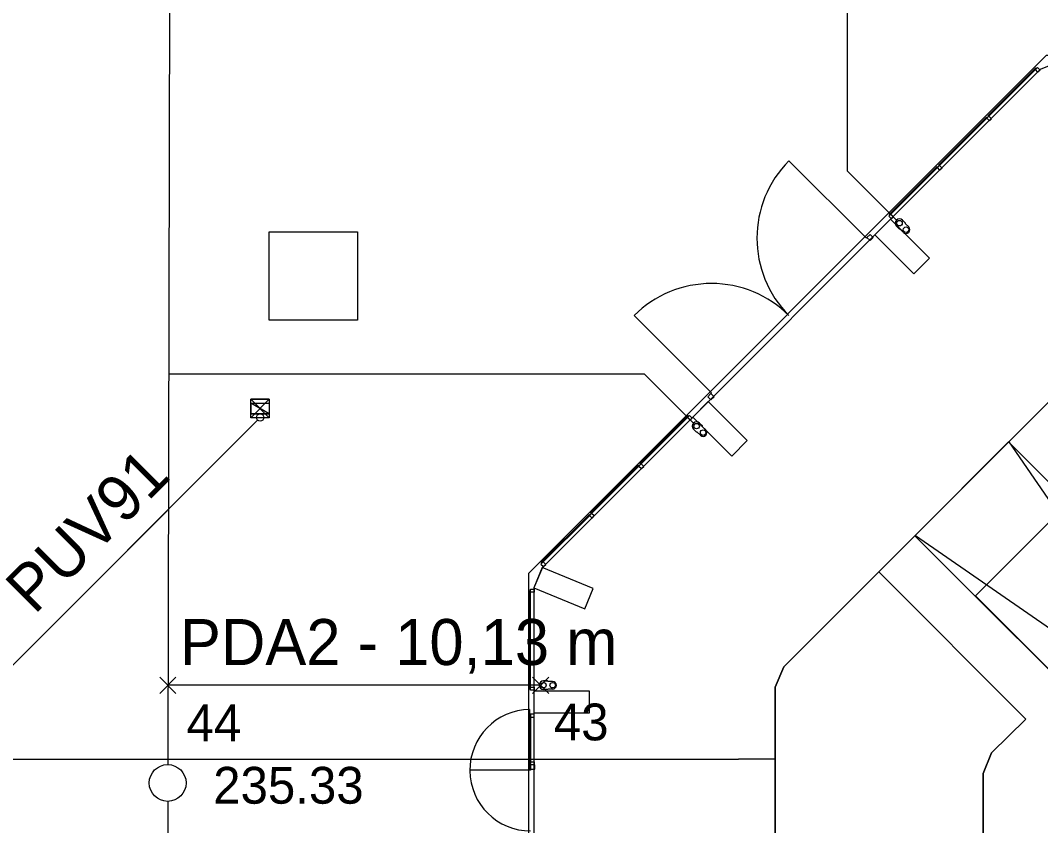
# Model space of a CAD drawing. Extents: x -264234 to -263604, y -1242346 to -1242049.
# Drawn here: x -263922.86 to -263895.13, y -1242108.24 to -1242086.36 of the extents above; entities that cross this region are included whole.
import ezdxf

# ---------------------------------------------------------------- set-up
doc = ezdxf.new("R2010")
doc.units = 0
for name, color, linetype in [('KFA_BODY_CISLO', 7, 'Continuous'), ('KFA_BODY_SYMBOL', 7, 'Continuous'), ('KFA_BODY_VYSKA', 7, 'Continuous'), ('KFA_DAZDOVA_KANALIZACIA_pripojky_tA_tC', 7, 'Continuous'), ('KFA_DAZDOVA_KANALIZACIA_pripojky_tA_tC_popis', 7, 'Continuous'), ('KFA_JESTV_IS_DSP_-_KANAL_DAZD', 7, 'Continuous'), ('KFA_SITUACIA_DSP', 7, 'Continuous'), ('KFA_SO_40-2-II_DK_PRIPOJKY_UV_PROJEKT', 7, 'Continuous'), ('KFA_SO_40-2-II_DK_PRIPOJKY_UV_PROJEKT_popis', 7, 'Continuous'), ('KFA_SO_40-2-II_DK_UV_PROJEKT', 7, 'Continuous')]:
    doc.layers.add(name, color=color, linetype=linetype)

msp = doc.modelspace()

# ---------------------------------------------------------------- linework, layer by layer
at = {"layer": 'KFA_BODY_SYMBOL'}
for p, q in [((-263919.072, -1242104.649), (-263918.63, -1242104.207)), ((-263918.63, -1242104.649), (-263919.072, -1242104.207)), ((-263908.939, -1242104.648), (-263908.497, -1242104.206)), ((-263908.497, -1242104.648), (-263908.939, -1242104.206))]:
    msp.add_line(p, q, dxfattribs=at)
at = {"layer": 'KFA_DAZDOVA_KANALIZACIA_pripojky_tA_tC'}
msp.add_line((-263908.718, -1242104.427), (-263918.851, -1242104.428), dxfattribs=at)
at = {"layer": 'KFA_JESTV_IS_DSP_-_KANAL_DAZD'}
for p, q in [((-263918.803, -1242082.338), (-263918.855, -1242106.583)), ((-263918.855, -1242107.583), (-263918.765, -1242151.564))]:
    msp.add_line(p, q, dxfattribs=at)
msp.add_circle((-263918.856, -1242107.083), 0.5, dxfattribs=at)
at = {"layer": 'KFA_SITUACIA_DSP'}
for p, q in [((-263900.379, -1242090.456), (-263900.379, -1242081.705)), ((-263908.663, -1242101.215), (-263895.135, -1242087.687)), ((-263895.258, -1242087.647), (-263896.566, -1242088.955)), ((-263896.548, -1242088.973), (-263895.24, -1242087.665)), ((-263895.273, -1242087.698), (-263895.245, -1242087.67)), ((-263895.202, -1242087.769), (-263895.273, -1242087.698)), ((-263895.24, -1242087.665), (-263895.258, -1242087.647)), ((-263895.245, -1242087.67), (-263895.216, -1242087.641)), ((-263895.216, -1242087.641), (-263895.146, -1242087.712)), ((-263895.135, -1242087.687), (-263894.581, -1242087.457)), ((-263895.146, -1242087.712), (-263895.202, -1242087.769)), ((-263897.906, -1242090.295), (-263896.598, -1242088.987)), ((-263896.58, -1242089.005), (-263897.888, -1242090.313)), ((-263896.598, -1242088.987), (-263896.58, -1242089.005)), ((-263896.592, -1242089.017), (-263896.564, -1242088.989)), ((-263896.522, -1242089.088), (-263896.592, -1242089.017)), ((-263896.566, -1242088.955), (-263896.548, -1242088.973)), ((-263896.564, -1242088.989), (-263896.536, -1242088.96)), ((-263896.536, -1242088.96), (-263896.465, -1242089.031)), ((-263896.465, -1242089.031), (-263896.522, -1242089.088)), ((-263899.866, -1242092.276), (-263901.97, -1242090.173)), ((-263899.018, -1242091.817), (-263900.379, -1242090.456)), ((-263899.25, -1242091.639), (-263897.942, -1242090.331)), ((-263897.924, -1242090.349), (-263899.232, -1242091.657)), ((-263897.942, -1242090.331), (-263897.924, -1242090.349)), ((-263897.936, -1242090.361), (-263897.908, -1242090.333)), ((-263897.865, -1242090.432), (-263897.936, -1242090.361)), ((-263897.908, -1242090.333), (-263897.88, -1242090.304)), ((-263897.888, -1242090.313), (-263897.906, -1242090.295)), ((-263897.88, -1242090.304), (-263897.809, -1242090.375)), ((-263897.809, -1242090.375), (-263897.865, -1242090.432)), ((-263899.207, -1242091.764), (-263899.631, -1242092.188)), ((-263899.255, -1242091.68), (-263899.227, -1242091.652)), ((-263899.185, -1242091.751), (-263899.255, -1242091.68)), ((-263899.232, -1242091.657), (-263899.25, -1242091.639)), ((-263899.227, -1242091.652), (-263899.199, -1242091.624)), ((-263898.147, -1242092.824), (-263899.207, -1242091.764)), ((-263899.199, -1242091.624), (-263899.128, -1242091.694)), ((-263899.128, -1242091.694), (-263899.185, -1242091.751)), ((-263898.804, -1242091.866), (-263898.882, -1242091.787)), ((-263916.093, -1242092.107), (-263913.693, -1242092.107)), ((-263916.093, -1242094.507), (-263916.093, -1242092.107)), ((-263913.693, -1242092.107), (-263913.693, -1242094.507)), ((-263898.969, -1242092.031), (-263899.047, -1242091.953)), ((-263899.047, -1242091.953), (-263898.969, -1242092.031)), ((-263898.949, -1242092.031), (-263898.969, -1242092.031)), ((-263898.861, -1242092.119), (-263898.949, -1242092.031)), ((-263898.804, -1242091.885), (-263898.804, -1242091.866)), ((-263898.715, -1242091.974), (-263898.804, -1242091.885)), ((-263899.849, -1242092.259), (-263899.866, -1242092.276)), ((-263899.764, -1242092.174), (-263899.849, -1242092.259)), ((-263899.849, -1242092.259), (-263899.764, -1242092.344)), ((-263899.679, -1242092.259), (-263899.764, -1242092.174)), ((-263899.764, -1242092.344), (-263899.679, -1242092.259)), ((-263899.631, -1242092.188), (-263898.571, -1242093.249)), ((-263898.571, -1242093.249), (-263898.147, -1242092.824)), ((-263913.693, -1242094.507), (-263916.093, -1242094.507)), ((-263904.074, -1242096.484), (-263906.177, -1242094.38)), ((-263905.894, -1242095.971), (-263918.832, -1242095.971)), ((-263904.533, -1242097.332), (-263905.894, -1242095.971)), ((-263904.176, -1242096.586), (-263904.091, -1242096.501)), ((-263904.091, -1242096.501), (-263904.074, -1242096.484)), ((-263904.091, -1242096.501), (-263904.006, -1242096.586)), ((-263916.593, -1242097.052), (-263916.593, -1242096.762)), ((-263916.593, -1242096.762), (-263916.093, -1242096.762)), ((-263916.093, -1242097.052), (-263916.593, -1242096.762)), ((-263916.093, -1242097.052), (-263916.593, -1242096.762)), ((-263916.593, -1242096.762), (-263916.593, -1242097.052)), ((-263916.093, -1242096.762), (-263916.093, -1242097.052)), ((-263904.586, -1242097.143), (-263904.162, -1242096.719)), ((-263904.091, -1242096.671), (-263904.176, -1242096.586)), ((-263904.162, -1242096.719), (-263903.101, -1242097.779)), ((-263904.006, -1242096.586), (-263904.091, -1242096.671)), ((-263916.093, -1242097.052), (-263916.593, -1242097.052)), ((-263916.593, -1242097.052), (-263916.093, -1242097.052)), ((-263904.711, -1242097.1), (-263906.019, -1242098.408)), ((-263906.001, -1242098.426), (-263904.693, -1242097.118)), ((-263904.698, -1242097.123), (-263904.726, -1242097.151)), ((-263904.693, -1242097.118), (-263904.711, -1242097.1)), ((-263904.67, -1242097.095), (-263904.698, -1242097.123)), ((-263904.599, -1242097.165), (-263904.67, -1242097.095)), ((-263916.414, -1242097.223), (-263926.239, -1242107.049)), ((-263904.726, -1242097.151), (-263904.656, -1242097.222)), ((-263904.656, -1242097.222), (-263904.599, -1242097.165)), ((-263903.526, -1242098.203), (-263904.586, -1242097.143)), ((-263904.319, -1242097.381), (-263904.397, -1242097.303)), ((-263904.319, -1242097.401), (-263904.319, -1242097.381)), ((-263904.231, -1242097.489), (-263904.319, -1242097.401)), ((-263904.484, -1242097.547), (-263904.563, -1242097.468)), ((-263904.563, -1242097.468), (-263904.484, -1242097.547)), ((-263904.465, -1242097.547), (-263904.484, -1242097.547)), ((-263904.376, -1242097.635), (-263904.465, -1242097.547)), ((-263903.101, -1242097.779), (-263903.526, -1242098.203)), ((-263906.055, -1242098.444), (-263907.363, -1242099.752)), ((-263907.345, -1242099.77), (-263906.037, -1242098.462)), ((-263906.037, -1242098.462), (-263906.055, -1242098.444)), ((-263906.017, -1242098.442), (-263906.046, -1242098.47)), ((-263906.046, -1242098.47), (-263905.975, -1242098.541)), ((-263906.019, -1242098.408), (-263906.001, -1242098.426)), ((-263905.989, -1242098.414), (-263906.017, -1242098.442)), ((-263905.918, -1242098.485), (-263905.989, -1242098.414)), ((-263905.975, -1242098.541), (-263905.918, -1242098.485)), ((-263908.703, -1242101.092), (-263907.395, -1242099.784)), ((-263907.377, -1242099.802), (-263908.685, -1242101.11)), ((-263907.395, -1242099.784), (-263907.377, -1242099.802)), ((-263907.361, -1242099.786), (-263907.39, -1242099.814)), ((-263907.39, -1242099.814), (-263907.319, -1242099.885)), ((-263907.363, -1242099.752), (-263907.345, -1242099.77)), ((-263907.333, -1242099.758), (-263907.361, -1242099.786)), ((-263907.262, -1242099.828), (-263907.333, -1242099.758)), ((-263907.319, -1242099.885), (-263907.262, -1242099.828)), ((-263908.674, -1242101.225), (-263908.903, -1242101.779)), ((-263908.893, -1242101.769), (-263908.663, -1242101.215)), ((-263908.68, -1242101.105), (-263908.709, -1242101.134)), ((-263908.709, -1242101.134), (-263908.638, -1242101.204)), ((-263908.685, -1242101.11), (-263908.703, -1242101.092)), ((-263908.652, -1242101.077), (-263908.68, -1242101.105)), ((-263907.288, -1242101.799), (-263908.674, -1242101.225)), ((-263908.581, -1242101.148), (-263908.652, -1242101.077)), ((-263908.638, -1242101.204), (-263908.581, -1242101.148)), ((-263899.53, -1242101.345), (-263902.113, -1242103.928)), ((-263895.529, -1242105.347), (-263899.53, -1242101.345)), ((-263908.993, -1242101.859), (-263908.993, -1242101.819)), ((-263908.993, -1242101.819), (-263908.893, -1242101.819)), ((-263908.903, -1242101.779), (-263907.518, -1242102.353)), ((-263908.893, -1242125.432), (-263908.893, -1242101.769)), ((-263908.893, -1242101.819), (-263908.893, -1242101.899)), ((-263907.518, -1242102.353), (-263907.288, -1242101.799)), ((-263909.018, -1242101.872), (-263909.018, -1242104.522)), ((-263908.993, -1242101.872), (-263909.018, -1242101.872)), ((-263908.993, -1242101.899), (-263908.993, -1242101.859)), ((-263908.993, -1242104.522), (-263908.993, -1242101.872)), ((-263908.893, -1242101.899), (-263908.993, -1242101.899)), ((-263902.113, -1242103.928), (-263902.343, -1242104.482)), ((-263908.643, -1242104.31), (-263908.532, -1242104.31)), ((-263908.532, -1242104.31), (-263908.643, -1242104.31)), ((-263908.518, -1242104.324), (-263908.532, -1242104.31)), ((-263908.393, -1242104.324), (-263908.518, -1242104.324)), ((-263908.718, -1242104.427), (-263918.846, -1242104.427)), ((-263909.018, -1242104.522), (-263908.993, -1242104.522)), ((-263908.993, -1242104.522), (-263908.993, -1242104.482)), ((-263908.993, -1242104.482), (-263908.893, -1242104.482)), ((-263908.993, -1242104.562), (-263908.993, -1242104.522)), ((-263908.893, -1242104.562), (-263908.993, -1242104.562)), ((-263908.898, -1242105.182), (-263908.898, -1242104.582)), ((-263908.898, -1242104.582), (-263907.398, -1242104.582)), ((-263908.893, -1242104.482), (-263908.893, -1242104.562)), ((-263908.532, -1242104.544), (-263908.643, -1242104.544)), ((-263908.518, -1242104.53), (-263908.532, -1242104.544)), ((-263908.393, -1242104.53), (-263908.518, -1242104.53)), ((-263907.398, -1242104.582), (-263907.398, -1242105.182)), ((-263902.343, -1242104.482), (-263902.343, -1242120.37)), ((-263909.018, -1242105.087), (-263909.018, -1242106.737)), ((-263909.018, -1242106.552), (-263909.018, -1242105.252)), ((-263909.018, -1242105.252), (-263908.993, -1242105.252)), ((-263908.893, -1242105.212), (-263908.993, -1242105.212)), ((-263908.993, -1242105.212), (-263908.993, -1242105.252)), ((-263908.993, -1242105.252), (-263908.993, -1242106.552)), ((-263908.993, -1242105.252), (-263908.993, -1242105.292)), ((-263908.993, -1242105.292), (-263908.893, -1242105.292)), ((-263907.398, -1242105.182), (-263908.898, -1242105.182)), ((-263908.893, -1242105.292), (-263908.893, -1242105.212)), ((-263896.465, -1242106.268), (-263895.529, -1242105.347)), ((-263896.693, -1242106.822), (-263896.465, -1242106.268)), ((-263923.393, -1242106.432), (-263903.343, -1242106.432)), ((-263908.993, -1242106.552), (-263909.018, -1242106.552)), ((-263908.993, -1242106.552), (-263908.993, -1242106.512)), ((-263908.993, -1242106.512), (-263908.893, -1242106.512)), ((-263908.993, -1242106.592), (-263908.993, -1242106.552)), ((-263908.893, -1242106.512), (-263908.893, -1242106.592)), ((-263902.343, -1242106.432), (-263903.343, -1242106.432)), ((-263908.993, -1242106.737), (-263910.643, -1242106.737)), ((-263908.893, -1242106.592), (-263908.993, -1242106.592)), ((-263908.873, -1242106.592), (-263908.993, -1242106.592)), ((-263908.993, -1242106.592), (-263908.993, -1242106.712)), ((-263908.993, -1242106.712), (-263908.993, -1242106.737)), ((-263908.993, -1242106.712), (-263908.873, -1242106.712)), ((-263908.873, -1242106.712), (-263908.873, -1242106.592)), ((-263896.693, -1242120.37), (-263896.693, -1242106.822))]:
    msp.add_line(p, q, dxfattribs=at)
for points in [[(-263794.893, -1242227.382), (-263808.968, -1242241.457), (-263894.968, -1242241.457), (-263909.043, -1242227.382), (-263909.043, -1242196.333), (-263914.143, -1242196.333), (-263914.143, -1242132.433), (-263909.043, -1242132.433), (-263909.043, -1242101.382), (-263894.968, -1242087.307), (-263808.968, -1242087.307), (-263794.893, -1242101.382), (-263794.893, -1242227.382)], [(-263909.043, -1242125.432), (-263902.343, -1242125.432), (-263902.343, -1242104.482), (-263902.112, -1242103.927), (-263898.54, -1242100.355), (-263895.995, -1242097.81), (-263892.423, -1242094.238), (-263891.868, -1242094.007), (-263812.071, -1242094.007), (-263811.513, -1242094.238), (-263801.823, -1242103.927), (-263801.593, -1242104.482), (-263801.593, -1242224.282), (-263801.824, -1242224.838), (-263805.392, -1242228.407)], [(-263891.681, -1242108.095), (-263894.08, -1242107.101), (-263892.944, -1242105.964), (-263898.552, -1242100.364), (-263896.003, -1242097.814), (-263890.399, -1242103.418), (-263889.262, -1242102.282), (-263888.268, -1242104.681), (-263891.681, -1242108.095)], [(-263898.54, -1242100.355), (-263895.995, -1242097.81), (-263890.341, -1242106.025), (-263898.533, -1242100.366)], [(-263893.618, -1242181.432), (-263893.618, -1242147.332), (-263892.018, -1242147.332), (-263892.018, -1242108.434), (-263891.673, -1242108.09), (-263894.073, -1242107.096), (-263892.937, -1242105.959), (-263896.896, -1242101.999), (-263894.351, -1242099.454), (-263890.391, -1242103.413), (-263889.254, -1242102.277), (-263888.26, -1242104.677), (-263887.916, -1242104.332), (-263816.02, -1242104.332), (-263815.675, -1242104.677), (-263814.681, -1242102.277), (-263813.545, -1242103.413), (-263809.585, -1242099.454), (-263807.039, -1242101.999), (-263810.999, -1242105.959), (-263809.862, -1242107.096), (-263812.262, -1242108.09), (-263811.918, -1242108.434), (-263811.918, -1242220.33)]]:
    msp.add_lwpolyline(points, dxfattribs=at)
msp.add_lwpolyline([(-263902.343, -1242120.37), (-263902.343, -1242104.482), (-263902.113, -1242103.928), (-263899.53, -1242101.345), (-263895.529, -1242105.347), (-263896.465, -1242106.268), (-263896.693, -1242106.822), (-263896.693, -1242120.37)], close=True, dxfattribs=at)
for centre, radius in [((-263898.965, -1242091.87), 0.075), ((-263898.788, -1242092.047), 0.075), ((-263916.343, -1242097.152), 0.1), ((-263904.48, -1242097.385), 0.075), ((-263904.303, -1242097.562), 0.075), ((-263908.643, -1242104.427), 0.075), ((-263908.393, -1242104.427), 0.075)]:
    msp.add_circle(centre, radius, dxfattribs=at)
for centre, radius, start, end in [((-263899.866, -1242092.276), 2.975, 135.0001, 225.0001), ((-263898.965, -1242091.87), 0.117, 45, 225), ((-263898.788, -1242092.047), 0.103, 225, 45), ((-263904.074, -1242096.484), 2.975, 44.9999, 134.9999), ((-263904.48, -1242097.385), 0.117, 45, 225), ((-263904.303, -1242097.562), 0.103, 225, 45), ((-263908.643, -1242104.427), 0.117, 90, 270), ((-263908.393, -1242104.427), 0.103, 270, 90), ((-263908.993, -1242106.737), 1.65, 90.8682, 270)]:
    msp.add_arc(centre, radius, start, end, dxfattribs=at)
at = {"layer": 'KFA_SO_40-2-II_DK_PRIPOJKY_UV_PROJEKT'}
msp.add_lwpolyline([(-263916.414, -1242097.223), (-263926.239, -1242107.049)], dxfattribs=at)
at = {"layer": 'KFA_SO_40-2-II_DK_UV_PROJEKT'}
msp.add_lwpolyline([(-263916.593, -1242097.157), (-263916.593, -1242096.657), (-263916.093, -1242096.657), (-263916.093, -1242097.157), (-263916.593, -1242097.157), (-263916.093, -1242096.657), (-263916.593, -1242096.657), (-263916.093, -1242097.157)], dxfattribs=at)

# ---------------------------------------------------------------- texts
at = {"layer": 'KFA_BODY_CISLO'}
for s, p in [('44', (-263918.342, -1242105.95)), ('43', (-263908.36, -1242105.925))]:
    msp.add_text(s, height=1, dxfattribs=at).set_placement(p)
at = {"layer": 'KFA_BODY_VYSKA'}
msp.add_text('235.33', height=1, dxfattribs=at).set_placement((-263917.619, -1242107.646))
at = {"layer": 'KFA_DAZDOVA_KANALIZACIA_pripojky_tA_tC_popis'}
msp.add_text('PDA2 - 10,13 m', height=1.25, dxfattribs=at).set_placement((-263918.524, -1242103.878))
at = {"layer": 'KFA_SO_40-2-II_DK_PRIPOJKY_UV_PROJEKT_popis'}
msp.add_text('PUV91', height=1.25, rotation=45, dxfattribs=at).set_placement((-263922.479, -1242102.529))

doc.saveas('drawing.dxf')
